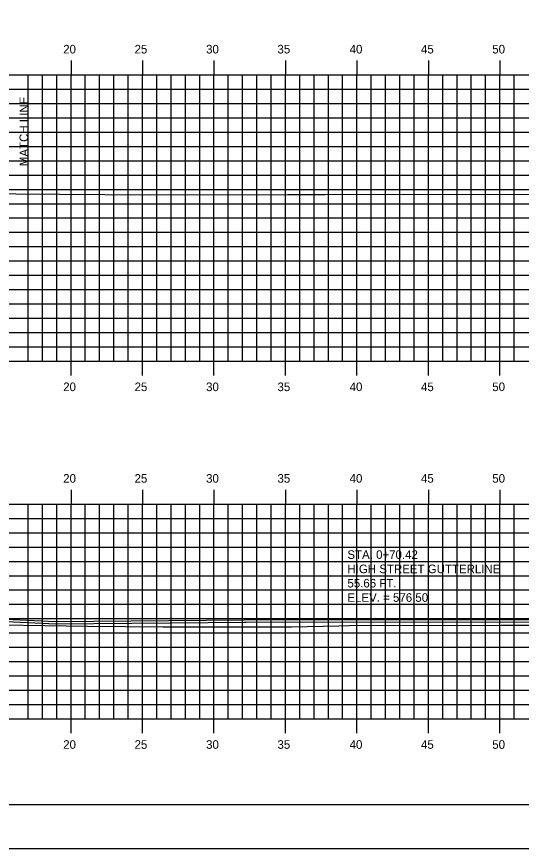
# Model space of a CAD drawing. Extents: x 1048345 to 1048515, y 781148 to 781258.
# Drawn here: x 1048444 to 1048479.3, y 781148.2 to 781206.3 of the extents above; entities that cross this region are included whole.
import ezdxf

# ---------------------------------------------------------------- set-up
doc = ezdxf.new("R2010")
doc.units = 0
for name, color, linetype in [('BORDER', 7, 'Continuous'), ('D_Roadway_SubGrade', 7, 'Continuous'), ('D_Text_Standard', 7, 'Continuous'), ('E_ROW_Line', 7, 'Continuous'), ('H_V ANNOTATION', 7, 'Continuous'), ('MAJOR', 7, 'Continuous'), ('MINOR', 7, 'Continuous'), ('PLOT BOUNDARY', 7, 'Continuous'), ('S_Roadway_Centerline', 7, 'Continuous')]:
    doc.layers.add(name, color=color, linetype=linetype)

msp = doc.modelspace()

# ---------------------------------------------------------------- linework, layer by layer
at = {"layer": 'BORDER'}
msp.add_lwpolyline([(1048352.833, 781151.252), (1048512.833, 781151.252), (1048512.833, 781256.252), (1048352.833, 781256.252)], close=True, dxfattribs=at)
at = {"layer": 'D_Roadway_SubGrade'}
for p, q in [((1048442.727, 781164.24), (1048446.775, 781164.052)), ((1048446.768, 781163.889), (1048460.081, 781164.01))]:
    msp.add_line(p, q, dxfattribs=at)
for points in [[(1048442.814, 781164.072), (1048446.768, 781163.889)], [(1048446.775, 781164.052), (1048459.936, 781164.172), (1048482.6, 781164.2)], [(1048459.938, 781164.009), (1048482.516, 781164.032)]]:
    msp.add_lwpolyline(points, dxfattribs=at)
at = {"layer": 'MAJOR'}
for p, q in [((1048447.832, 781203.254), (1048447.832, 781202.252)), ((1048452.832, 781203.254), (1048452.832, 781202.252)), ((1048457.832, 781203.254), (1048457.832, 781202.252)), ((1048462.832, 781203.254), (1048462.832, 781202.252)), ((1048467.832, 781203.254), (1048467.832, 781202.252)), ((1048472.832, 781203.254), (1048472.832, 781202.252)), ((1048477.832, 781203.254), (1048477.832, 781202.252)), ((1048357.832, 781202.252), (1048497.832, 781202.252)), ((1048357.832, 781202.252), (1048497.832, 781202.252)), ((1048357.832, 781202.252), (1048497.832, 781202.252)), ((1048447.832, 781182.252), (1048447.832, 781202.252)), ((1048447.832, 781182.252), (1048447.832, 781202.252)), ((1048452.832, 781182.252), (1048452.832, 781202.252)), ((1048452.832, 781182.252), (1048452.832, 781202.252)), ((1048457.832, 781182.252), (1048457.832, 781202.252)), ((1048457.832, 781182.252), (1048457.832, 781202.252)), ((1048462.832, 781182.252), (1048462.832, 781202.252)), ((1048462.832, 781182.252), (1048462.832, 781202.252)), ((1048467.832, 781182.252), (1048467.832, 781202.252)), ((1048467.832, 781182.252), (1048467.832, 781202.252)), ((1048472.832, 781182.252), (1048472.832, 781202.252)), ((1048472.832, 781182.252), (1048472.832, 781202.252)), ((1048477.832, 781182.252), (1048477.832, 781202.252)), ((1048477.832, 781182.252), (1048477.832, 781202.252)), ((1048357.832, 781197.252), (1048497.832, 781197.252)), ((1048357.832, 781197.252), (1048497.832, 781197.252)), ((1048357.832, 781192.252), (1048497.832, 781192.252)), ((1048357.832, 781192.252), (1048497.832, 781192.252)), ((1048357.832, 781187.252), (1048497.832, 781187.252)), ((1048357.832, 781187.252), (1048497.832, 781187.252)), ((1048357.832, 781182.252), (1048497.832, 781182.252)), ((1048357.832, 781182.252), (1048497.832, 781182.252)), ((1048357.832, 781182.252), (1048497.832, 781182.252)), ((1048447.832, 781181.25), (1048447.832, 781182.252)), ((1048452.832, 781181.25), (1048452.832, 781182.252)), ((1048457.832, 781181.25), (1048457.832, 781182.252)), ((1048462.832, 781181.25), (1048462.832, 781182.252)), ((1048467.832, 781181.25), (1048467.832, 781182.252)), ((1048472.832, 781181.25), (1048472.832, 781182.252)), ((1048477.832, 781181.25), (1048477.832, 781182.252)), ((1048447.832, 781173.254), (1048447.832, 781172.252)), ((1048452.832, 781173.254), (1048452.832, 781172.252)), ((1048457.832, 781173.254), (1048457.832, 781172.252)), ((1048462.832, 781173.254), (1048462.832, 781172.252)), ((1048467.832, 781173.254), (1048467.832, 781172.252)), ((1048472.832, 781173.254), (1048472.832, 781172.252)), ((1048477.832, 781173.254), (1048477.832, 781172.252)), ((1048357.832, 781172.252), (1048497.832, 781172.252)), ((1048357.832, 781172.252), (1048497.832, 781172.252)), ((1048447.832, 781157.252), (1048447.832, 781172.252)), ((1048452.832, 781157.252), (1048452.832, 781172.252)), ((1048457.832, 781157.252), (1048457.832, 781172.252)), ((1048462.832, 781157.252), (1048462.832, 781172.252)), ((1048467.832, 781157.252), (1048467.832, 781172.252)), ((1048472.832, 781157.252), (1048472.832, 781172.252)), ((1048477.832, 781157.252), (1048477.832, 781172.252)), ((1048357.832, 781167.252), (1048497.832, 781167.252)), ((1048357.832, 781162.252), (1048497.832, 781162.252)), ((1048357.832, 781157.252), (1048497.832, 781157.252)), ((1048357.832, 781157.252), (1048497.832, 781157.252)), ((1048447.832, 781156.25), (1048447.832, 781157.252)), ((1048452.832, 781156.25), (1048452.832, 781157.252)), ((1048457.832, 781156.25), (1048457.832, 781157.252)), ((1048462.832, 781156.25), (1048462.832, 781157.252)), ((1048467.832, 781156.25), (1048467.832, 781157.252)), ((1048472.832, 781156.25), (1048472.832, 781157.252)), ((1048477.832, 781156.25), (1048477.832, 781157.252))]:
    msp.add_line(p, q, dxfattribs=at)
at = {"layer": 'MINOR'}
for p, q in [((1048444.832, 781182.252), (1048444.832, 781202.252)), ((1048444.832, 781182.252), (1048444.832, 781202.252)), ((1048445.832, 781182.252), (1048445.832, 781202.252)), ((1048445.832, 781182.252), (1048445.832, 781202.252)), ((1048446.832, 781182.252), (1048446.832, 781202.252)), ((1048446.832, 781182.252), (1048446.832, 781202.252)), ((1048448.832, 781182.252), (1048448.832, 781202.252)), ((1048448.832, 781182.252), (1048448.832, 781202.252)), ((1048449.832, 781182.252), (1048449.832, 781202.252)), ((1048449.832, 781182.252), (1048449.832, 781202.252)), ((1048450.832, 781182.252), (1048450.832, 781202.252)), ((1048450.832, 781182.252), (1048450.832, 781202.252)), ((1048451.832, 781182.252), (1048451.832, 781202.252)), ((1048451.832, 781182.252), (1048451.832, 781202.252)), ((1048453.832, 781182.252), (1048453.832, 781202.252)), ((1048453.832, 781182.252), (1048453.832, 781202.252)), ((1048454.832, 781182.252), (1048454.832, 781202.252)), ((1048454.832, 781182.252), (1048454.832, 781202.252)), ((1048455.832, 781182.252), (1048455.832, 781202.252)), ((1048455.832, 781182.252), (1048455.832, 781202.252)), ((1048456.832, 781182.252), (1048456.832, 781202.252)), ((1048456.832, 781182.252), (1048456.832, 781202.252)), ((1048458.832, 781182.252), (1048458.832, 781202.252)), ((1048458.832, 781182.252), (1048458.832, 781202.252)), ((1048459.832, 781182.252), (1048459.832, 781202.252)), ((1048459.832, 781182.252), (1048459.832, 781202.252)), ((1048460.832, 781182.252), (1048460.832, 781202.252)), ((1048460.832, 781182.252), (1048460.832, 781202.252)), ((1048461.832, 781182.252), (1048461.832, 781202.252)), ((1048461.832, 781182.252), (1048461.832, 781202.252)), ((1048463.832, 781182.252), (1048463.832, 781202.252)), ((1048463.832, 781182.252), (1048463.832, 781202.252)), ((1048464.832, 781182.252), (1048464.832, 781202.252)), ((1048464.832, 781182.252), (1048464.832, 781202.252)), ((1048465.832, 781182.252), (1048465.832, 781202.252)), ((1048465.832, 781182.252), (1048465.832, 781202.252)), ((1048466.832, 781182.252), (1048466.832, 781202.252)), ((1048466.832, 781182.252), (1048466.832, 781202.252)), ((1048468.832, 781182.252), (1048468.832, 781202.252)), ((1048468.832, 781182.252), (1048468.832, 781202.252)), ((1048469.832, 781182.252), (1048469.832, 781202.252)), ((1048469.832, 781182.252), (1048469.832, 781202.252)), ((1048470.832, 781182.252), (1048470.832, 781202.252)), ((1048470.832, 781182.252), (1048470.832, 781202.252)), ((1048471.832, 781182.252), (1048471.832, 781202.252)), ((1048471.832, 781182.252), (1048471.832, 781202.252)), ((1048473.832, 781182.252), (1048473.832, 781202.252)), ((1048473.832, 781182.252), (1048473.832, 781202.252)), ((1048474.832, 781182.252), (1048474.832, 781202.252)), ((1048474.832, 781182.252), (1048474.832, 781202.252)), ((1048475.832, 781182.252), (1048475.832, 781202.252)), ((1048475.832, 781182.252), (1048475.832, 781202.252)), ((1048476.832, 781182.252), (1048476.832, 781202.252)), ((1048476.832, 781182.252), (1048476.832, 781202.252)), ((1048478.832, 781182.252), (1048478.832, 781202.252)), ((1048478.832, 781182.252), (1048478.832, 781202.252)), ((1048357.832, 781201.252), (1048497.832, 781201.252)), ((1048357.832, 781201.252), (1048497.832, 781201.252)), ((1048357.832, 781200.252), (1048497.832, 781200.252)), ((1048357.832, 781200.252), (1048497.832, 781200.252)), ((1048357.832, 781199.252), (1048497.832, 781199.252)), ((1048357.832, 781199.252), (1048497.832, 781199.252)), ((1048357.832, 781198.252), (1048497.832, 781198.252)), ((1048357.832, 781198.252), (1048497.832, 781198.252)), ((1048357.832, 781196.252), (1048497.832, 781196.252)), ((1048357.832, 781196.252), (1048497.832, 781196.252)), ((1048357.832, 781195.252), (1048497.832, 781195.252)), ((1048357.832, 781195.252), (1048497.832, 781195.252)), ((1048357.832, 781194.252), (1048497.832, 781194.252)), ((1048357.832, 781194.252), (1048497.832, 781194.252)), ((1048357.832, 781193.252), (1048497.832, 781193.252)), ((1048357.832, 781193.252), (1048497.832, 781193.252)), ((1048357.832, 781191.252), (1048497.832, 781191.252)), ((1048357.832, 781191.252), (1048497.832, 781191.252)), ((1048357.832, 781190.252), (1048497.832, 781190.252)), ((1048357.832, 781190.252), (1048497.832, 781190.252)), ((1048357.832, 781189.252), (1048497.832, 781189.252)), ((1048357.832, 781189.252), (1048497.832, 781189.252)), ((1048357.832, 781188.252), (1048497.832, 781188.252)), ((1048357.832, 781188.252), (1048497.832, 781188.252)), ((1048357.832, 781186.252), (1048497.832, 781186.252)), ((1048357.832, 781186.252), (1048497.832, 781186.252)), ((1048357.832, 781185.252), (1048497.832, 781185.252)), ((1048357.832, 781185.252), (1048497.832, 781185.252)), ((1048357.832, 781184.252), (1048497.832, 781184.252)), ((1048357.832, 781184.252), (1048497.832, 781184.252)), ((1048357.832, 781183.252), (1048497.832, 781183.252)), ((1048357.832, 781183.252), (1048497.832, 781183.252)), ((1048444.832, 781157.252), (1048444.832, 781172.252)), ((1048445.832, 781157.252), (1048445.832, 781172.252)), ((1048446.832, 781157.252), (1048446.832, 781172.252)), ((1048448.832, 781157.252), (1048448.832, 781172.252)), ((1048449.832, 781157.252), (1048449.832, 781172.252)), ((1048450.832, 781157.252), (1048450.832, 781172.252)), ((1048451.832, 781157.252), (1048451.832, 781172.252)), ((1048453.832, 781157.252), (1048453.832, 781172.252)), ((1048454.832, 781157.252), (1048454.832, 781172.252)), ((1048455.832, 781157.252), (1048455.832, 781172.252)), ((1048456.832, 781157.252), (1048456.832, 781172.252)), ((1048458.832, 781157.252), (1048458.832, 781172.252)), ((1048459.832, 781157.252), (1048459.832, 781172.252)), ((1048460.832, 781157.252), (1048460.832, 781172.252)), ((1048461.832, 781157.252), (1048461.832, 781172.252)), ((1048463.832, 781157.252), (1048463.832, 781172.252)), ((1048464.832, 781157.252), (1048464.832, 781172.252)), ((1048465.832, 781157.252), (1048465.832, 781172.252)), ((1048466.832, 781157.252), (1048466.832, 781172.252)), ((1048468.832, 781157.252), (1048468.832, 781172.252)), ((1048469.832, 781157.252), (1048469.832, 781172.252)), ((1048470.832, 781157.252), (1048470.832, 781172.252)), ((1048471.832, 781157.252), (1048471.832, 781172.252)), ((1048473.832, 781157.252), (1048473.832, 781172.252)), ((1048474.832, 781157.252), (1048474.832, 781172.252)), ((1048475.832, 781157.252), (1048475.832, 781172.252)), ((1048476.832, 781157.252), (1048476.832, 781172.252)), ((1048478.832, 781157.252), (1048478.832, 781172.252)), ((1048357.832, 781171.252), (1048497.832, 781171.252)), ((1048357.832, 781170.252), (1048497.832, 781170.252)), ((1048357.832, 781169.252), (1048497.832, 781169.252)), ((1048357.832, 781168.252), (1048497.832, 781168.252)), ((1048357.832, 781166.252), (1048497.832, 781166.252)), ((1048357.832, 781165.252), (1048497.832, 781165.252)), ((1048357.832, 781164.252), (1048497.832, 781164.252)), ((1048357.832, 781163.252), (1048497.832, 781163.252)), ((1048357.832, 781161.252), (1048497.832, 781161.252)), ((1048357.832, 781160.252), (1048497.832, 781160.252)), ((1048357.832, 781159.252), (1048497.832, 781159.252)), ((1048357.832, 781158.252), (1048497.832, 781158.252))]:
    msp.add_line(p, q, dxfattribs=at)
at = {"layer": 'PLOT BOUNDARY'}
msp.add_lwpolyline([(1048344.739, 781148.193), (1048514.739, 781148.193), (1048514.739, 781258.193), (1048344.739, 781258.193)], close=True, dxfattribs=at)
at = {"layer": 'S_Roadway_Centerline'}
for points in [[(1048378.404, 781193.971), (1048380.444, 781192.878), (1048381.518, 781192.487), (1048383.629, 781192.368), (1048383.98, 781192.382), (1048392.669, 781192.719), (1048401.451, 781193.061), (1048401.471, 781193.059), (1048406.922, 781193.087), (1048409.89, 781193.252), (1048415.467, 781193.603), (1048421.353, 781193.835), (1048427.506, 781194.095), (1048431.344, 781194.1), (1048434.132, 781194.08), (1048434.162, 781194.088), (1048439.882, 781194.008), (1048443.963, 781193.943), (1048453.31, 781193.879), (1048463.018, 781193.897), (1048464.051, 781193.889), (1048465.593, 781193.896), (1048488.39, 781193.918), (1048497.832, 781193.927)], [(1048439.979, 781163.865), (1048448.984, 781163.722), (1048454.288, 781163.686), (1048462.242, 781163.668), (1048463.252, 781163.68), (1048466.557, 781163.756), (1048467.285, 781163.777), (1048477.908, 781163.797), (1048479.45, 781163.793), (1048481.844, 781163.791), (1048497.16, 781163.754), (1048497.832, 781163.758)]]:
    msp.add_lwpolyline(points, dxfattribs=at)

# ---------------------------------------------------------------- texts
at = {"layer": 'D_Text_Standard'}
for s, p in [('STA. 0+70.42', (1048467.165, 781168.427)), ('HIGH STREET GUTTERLINE', (1048467.165, 781167.427)), ('55.66 FT.', (1048467.165, 781166.427)), ('ELEV. = 576.50', (1048467.165, 781165.426))]:
    msp.add_text(s, height=0.6, dxfattribs=at).set_placement(p)
at = {"layer": 'E_ROW_Line'}
msp.add_text('MATCH LINE', height=0.6, rotation=90, dxfattribs=at).set_placement((1048444.832, 781195.875))
at = {"layer": 'H_V ANNOTATION'}
for s, p in [('20', (1048447.286, 781203.752)), ('25', (1048452.278, 781203.752)), ('30', (1048457.281, 781203.752)), ('35', (1048462.273, 781203.752)), ('40', (1048467.319, 781203.752)), ('50', (1048477.297, 781203.752)), ('45', (1048472.311, 781203.752)), ('20', (1048447.286, 781180.152)), ('25', (1048452.278, 781180.152)), ('30', (1048457.281, 781180.152)), ('35', (1048462.273, 781180.152)), ('40', (1048467.319, 781180.152)), ('45', (1048472.311, 781180.152)), ('50', (1048477.297, 781180.152)), ('20', (1048447.286, 781173.752)), ('25', (1048452.278, 781173.752)), ('30', (1048457.281, 781173.752)), ('35', (1048462.273, 781173.752)), ('40', (1048467.319, 781173.752)), ('45', (1048472.311, 781173.752)), ('50', (1048477.297, 781173.752)), ('20', (1048447.286, 781155.152)), ('25', (1048452.278, 781155.152)), ('30', (1048457.281, 781155.152)), ('35', (1048462.273, 781155.152)), ('40', (1048467.319, 781155.152)), ('45', (1048472.311, 781155.152)), ('50', (1048477.297, 781155.152))]:
    msp.add_text(s, height=0.6, dxfattribs=at).set_placement(p)

doc.saveas('drawing.dxf')
